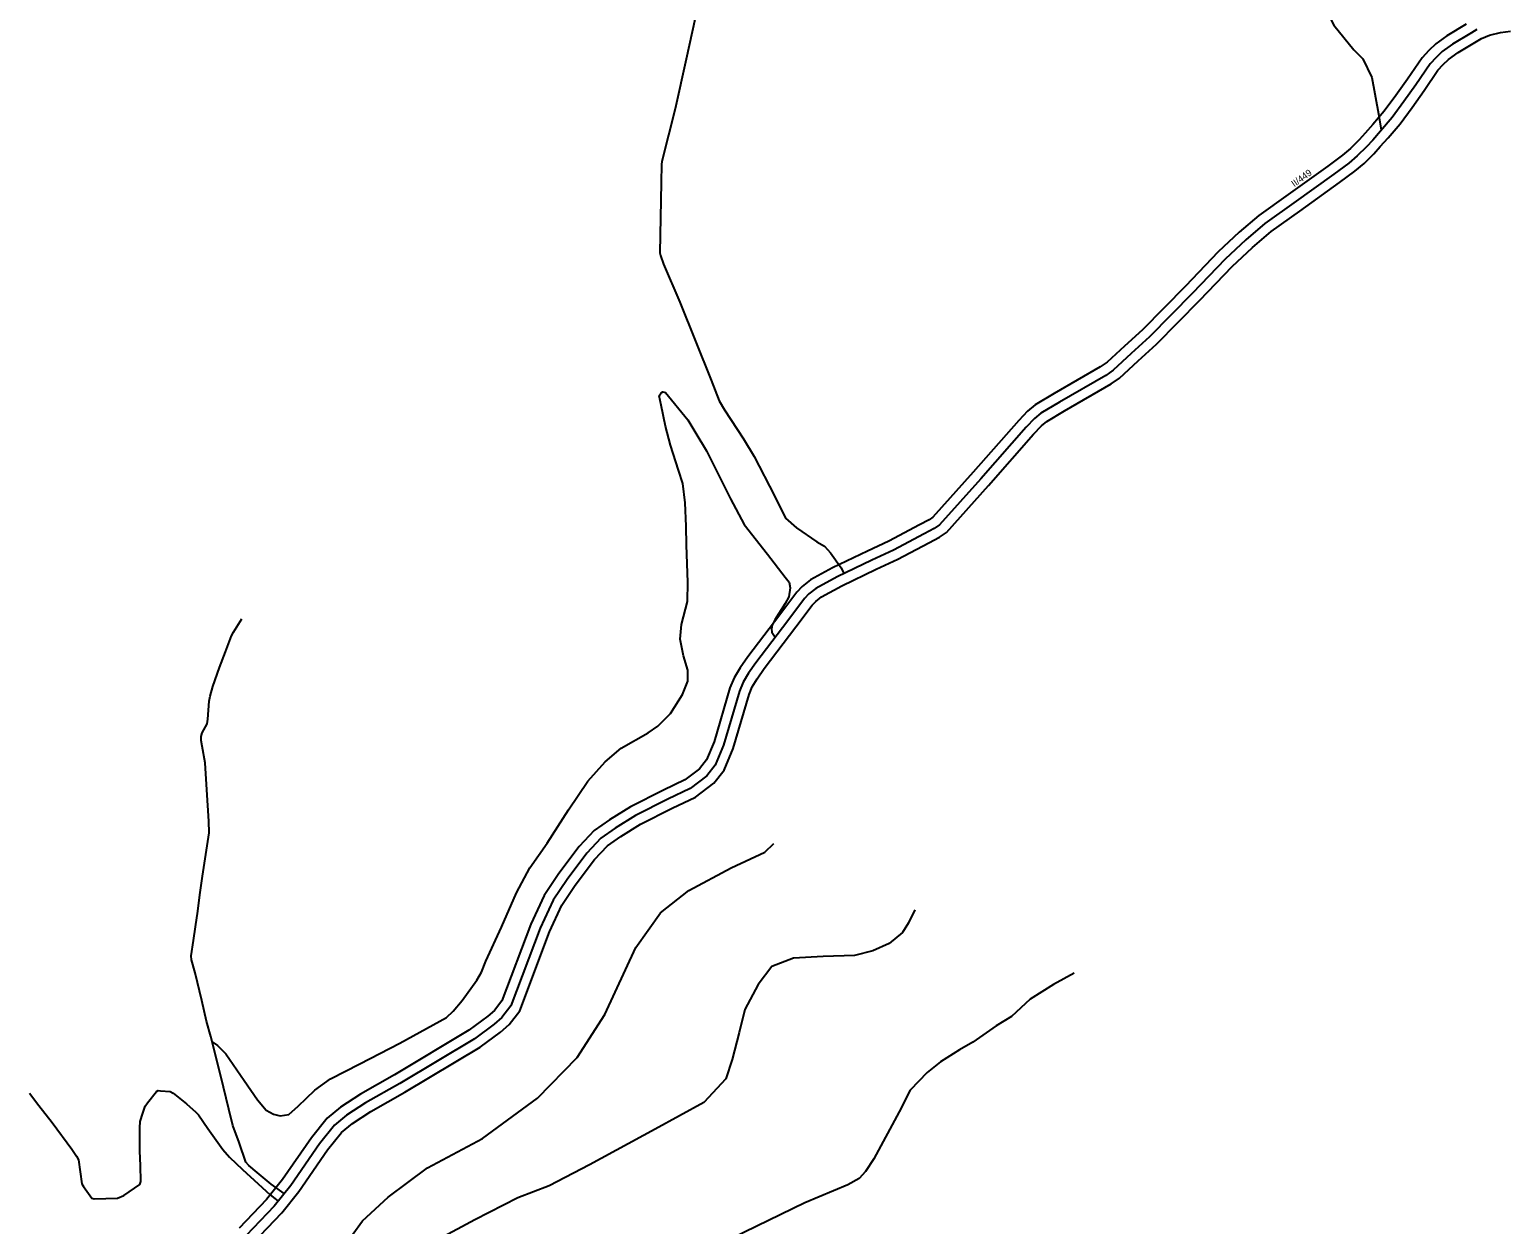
# Model space of a CAD drawing. Extents: x -547395 to -536032, y -1096268 to -1086572.
# Drawn here: x -545276 to -543076, y -1090100 to -1088325 of the extents above; entities that cross this region are included whole.
import ezdxf

# ---------------------------------------------------------------- set-up
doc = ezdxf.new("R2010")
doc.units = 0
for name, color, linetype in [('Vrstva 12', 7, 'Continuous'), ('Vrstva 5', 7, 'Continuous'), ('Vrstva 66', 7, 'Continuous')]:
    doc.layers.add(name, color=color, linetype=linetype)

msp = doc.modelspace()

# ---------------------------------------------------------------- linework, layer by layer
at = {"layer": 'Vrstva 12'}
for points in [[(-543412.7, -1088101.2), (-543404.2, -1088139.6), (-543379.7, -1088205.6), (-543357.3, -1088279.8), (-543338.3, -1088317.9), (-543308.3, -1088354.6), (-543295.1, -1088367.9), (-543281.5, -1088395.8), (-543271.6, -1088449.9), (-543267.8, -1088474.2)], [(-544286.7, -1088307.7), (-544300.1, -1088368.4), (-544316.8, -1088442.2), (-544336.3, -1088520.3), (-544337, -1088525.1), (-544337.3, -1088551.9), (-544339.2, -1088656.2), (-544338.5, -1088660.3), (-544333.8, -1088672.9), (-544309.6, -1088729.4), (-544263.2, -1088845.2), (-544251, -1088876.2), (-544243.3, -1088889.6), (-544215.1, -1088932.8), (-544199.2, -1088958.7), (-544169.2, -1089017.5), (-544152.8, -1089050.7), (-544136.4, -1089064.7), (-544106.2, -1089085.4), (-544094.6, -1089091.9), (-544085.8, -1089102.1), (-544070.2, -1089124.2), (-544066.1, -1089132.9)], [(-545004.1, -1089828.7), (-544996.4, -1089833.9), (-544983.8, -1089846.1), (-544956.6, -1089885.9), (-544937.2, -1089914.5), (-544924, -1089930.1), (-544913.4, -1089935.9), (-544903.2, -1089938.6), (-544890.6, -1089936.6), (-544876.7, -1089924), (-544851.6, -1089900.5), (-544828.8, -1089883.5), (-544784.9, -1089861.4), (-544725.6, -1089830.3), (-544656.2, -1089792.2), (-544646.4, -1089783), (-544632.8, -1089767), (-544611, -1089737.1), (-544604.2, -1089724.8), (-544597.8, -1089708.8), (-544574.5, -1089658.3), (-544552.1, -1089607.3), (-544532.7, -1089570.2), (-544506.5, -1089533.1), (-544475.1, -1089483.9), (-544446.5, -1089441.1), (-544420.7, -1089412.5), (-544396.9, -1089392.1), (-544356.8, -1089369.3), (-544342.3, -1089359.6), (-544323.3, -1089340.9), (-544305.9, -1089312.3), (-544297.8, -1089292.6), (-544297.8, -1089276.2), (-544304.2, -1089255.1), (-544309, -1089230), (-544307.1, -1089208.4), (-544298.3, -1089174.3), (-544297.9, -1089145.4), (-544299.7, -1089090.6), (-544300, -1089062.4), (-544301.5, -1089027.5), (-544305.3, -1088998.9), (-544311.7, -1088979.2), (-544323.6, -1088941.8), (-544331.1, -1088913.9), (-544337.4, -1088882.4), (-544340.4, -1088868.8), (-544337.4, -1088864.1), (-544334.7, -1088862.7), (-544330.9, -1088863.7), (-544297.9, -1088904.2), (-544285.7, -1088924.3), (-544269.9, -1088950.6), (-544234.2, -1089021.8), (-544214.2, -1089059.9), (-544179.3, -1089103.9), (-544153.1, -1089137.9), (-544147, -1089145.4), (-544145.7, -1089153.9), (-544147.7, -1089167.2), (-544153.2, -1089177), (-544168.5, -1089201.3), (-544172.4, -1089209.3), (-544173.3, -1089214.7), (-544172.8, -1089220), (-544167.9, -1089227.4)], [(-544897.3, -1090054), (-544916.5, -1090040), (-544937.6, -1090022.8), (-544950.1, -1090012.2), (-544954.2, -1090007.1), (-544964.4, -1089978), (-544973.4, -1089953), (-544979.4, -1089928.4), (-544991.7, -1089879.7), (-545006.1, -1089820.7), (-545012.6, -1089797.9), (-545019.8, -1089767), (-545029.8, -1089726), (-545034.8, -1089706.7), (-545035.3, -1089700.6), (-545031.9, -1089677.8), (-545029.2, -1089657.4), (-545025.6, -1089634.5), (-545022.7, -1089610.2), (-545018.8, -1089582.4), (-545008.9, -1089517.8), (-545009.1, -1089500.6), (-545012.2, -1089454), (-545014.9, -1089414.2), (-545019, -1089389), (-545020.5, -1089380.7), (-545020.5, -1089374.9), (-545019.1, -1089369.4), (-545011.7, -1089356.2), (-545011, -1089349), (-545008.9, -1089322.5), (-545007.2, -1089314.7), (-545003.2, -1089300.7), (-544993.3, -1089272.5), (-544984.6, -1089249.2), (-544975.5, -1089225.4), (-544972.4, -1089219.6), (-544960.2, -1089199.9)], [(-544809.5, -1090134), (-544780.9, -1090094.5), (-544742.8, -1090059.2), (-544684.4, -1090015.6), (-544602.8, -1089972.1), (-544521.2, -1089912.2), (-544462.1, -1089851.6), (-544421.3, -1089787.7), (-544375, -1089688.3), (-544338.3, -1089636.6), (-544296.2, -1089603.9), (-544233.6, -1089569.9), (-544183.3, -1089546.8), (-544169.8, -1089533.9)], [(-543960.7, -1089632.2), (-543970.2, -1089651.9), (-543979, -1089666.2), (-543998.7, -1089682.5), (-544023.2, -1089693.4), (-544050.4, -1089700.2), (-544096.6, -1089701.6), (-544140.8, -1089704.3), (-544172.8, -1089716.6), (-544193.2, -1089743.1), (-544212.9, -1089780.5), (-544221.7, -1089814.5), (-544231.9, -1089854.7), (-544241.4, -1089883.3), (-544274.1, -1089918.6), (-544346.1, -1089958.1), (-544444, -1090011.2), (-544503.9, -1090042.5), (-544550.1, -1090060.2), (-544614, -1090092.8), (-544666.7, -1090121.1)], [(-543724.1, -1089726.3), (-543754.6, -1089743.3), (-543789.3, -1089765), (-543817.2, -1089790.9), (-543839.6, -1089804.5), (-543874.3, -1089829), (-543894, -1089840.6), (-543922.6, -1089858.3), (-543942.3, -1089873.9), (-543967.4, -1089900.4), (-543983.8, -1089932.4), (-544021.5, -1090002.2), (-544033.7, -1090021.2), (-544043.2, -1090031.4), (-544060.2, -1090041), (-544124.2, -1090067.5), (-544267.6, -1090137.6)], [(-545275.5, -1089904.6), (-545261.7, -1089922.9), (-545242.2, -1089948.5), (-545212.9, -1089987.8), (-545205.7, -1089998.4), (-545202.8, -1090004), (-545197.7, -1090039.6), (-545195.6, -1090043.2), (-545182.9, -1090060.6), (-545179.5, -1090061.6), (-545144.8, -1090060.9), (-545135.4, -1090056.8), (-545112, -1090040.3), (-545110.3, -1090036.2), (-545110.8, -1090012.1), (-545111.6, -1089990.7), (-545111.9, -1089956.5), (-545111.4, -1089946.8), (-545107.3, -1089934.4), (-545103.7, -1089924.3), (-545100.6, -1089919.2), (-545086.8, -1089902.5), (-545084.4, -1089901), (-545080.9, -1089901.2), (-545066.9, -1089902.5), (-545062.2, -1089904.9), (-545042.3, -1089920.7), (-545028.4, -1089933), (-545024.4, -1089936.9), (-545010.9, -1089957.1), (-544988.7, -1089988.7), (-544978.6, -1089999.9), (-544959.1, -1090018.3), (-544936.1, -1090039.6), (-544918.4, -1090055.8), (-544911.2, -1090061.1), (-544906.2, -1090065.3)]]:
    msp.add_lwpolyline(points, dxfattribs=at)
at = {"layer": 'Vrstva 5'}
msp.add_lwpolyline([(-543125.6, -1088324.3), (-543133.9, -1088329.3), (-543161.9, -1088346.3), (-543177.3, -1088357.3), (-543186.3, -1088366), (-543195.3, -1088375.6), (-543216.3, -1088406.7), (-543234, -1088431.4), (-543251.7, -1088455.2), (-543269, -1088475.6), (-543280.4, -1088488.6), (-543289.7, -1088498.9), (-543303.4, -1088512.3), (-543316.1, -1088522.9), (-543338.4, -1088539.6), (-543397.5, -1088582), (-543440.5, -1088612.9), (-543468.9, -1088636.9), (-543499.6, -1088665.6), (-543548, -1088716.3), (-543612, -1088781.2), (-543639.1, -1088805.9), (-543665.8, -1088830.6), (-543677.1, -1088838.3), (-543745.8, -1088878.3), (-543773.2, -1088894.5), (-543782.9, -1088902.5), (-543795.2, -1088915.5), (-543862.6, -1088991.9), (-543923.7, -1089060.3), (-543931.7, -1089066), (-543946.7, -1089073.7), (-543992.4, -1089097.9), (-544024.4, -1089112.9), (-544075.8, -1089137.6), (-544107.5, -1089154.9), (-544117.9, -1089162.9), (-544124.5, -1089169.9), (-544149.2, -1089203), (-544196.6, -1089265.2), (-544207.6, -1089280.9), (-544215.6, -1089294.2), (-544221, -1089307.6), (-544244.7, -1089387.8), (-544257, -1089417.2), (-544269.7, -1089433.5), (-544294.4, -1089452.2), (-544327.4, -1089467.9), (-544375.5, -1089492.2), (-544405.8, -1089511.1), (-544426.8, -1089526.1), (-544447.9, -1089548.1), (-544477.2, -1089587.2), (-544497.9, -1089618.2), (-544516.9, -1089659.4), (-544560.6, -1089775.2), (-544574, -1089792.2), (-544585.3, -1089802.2), (-544614.7, -1089823.9), (-544725.8, -1089890.5), (-544776.5, -1089919.2), (-544805, -1089937.6), (-544822.8, -1089952.5), (-544844.8, -1089979.9), (-544887.7, -1090041.8), (-544912.1, -1090072.7), (-544953.7, -1090116.2)], dxfattribs=at)
at = {"layer": 'Vrstva 66'}
for points in [[(-543141.6, -1088316.4), (-543170.2, -1088333.8), (-543186.9, -1088345.7), (-543197, -1088355.5), (-543207.1, -1088366.3), (-543228.6, -1088398.1), (-543246.1, -1088422.5), (-543263.4, -1088445.9), (-543280.4, -1088465.8), (-543291.6, -1088478.6), (-543300.5, -1088488.5), (-543313.5, -1088501.2), (-543325.4, -1088511.2), (-543347.3, -1088527.5), (-543406.2, -1088569.8), (-543449.8, -1088601), (-543478.9, -1088625.7), (-543510.1, -1088654.9), (-543558.7, -1088705.9), (-543622.4, -1088770.4), (-543649.2, -1088794.9), (-543675.1, -1088818.8), (-543685.1, -1088825.6), (-543753.4, -1088865.4), (-543781.9, -1088882.2), (-543793.1, -1088891.5), (-543806.3, -1088905.4), (-543873.8, -1088982), (-543933.7, -1089049.1), (-543939.5, -1089053.1), (-543953.6, -1089060.4), (-543999.1, -1089084.4), (-544030.9, -1089099.3), (-544082.7, -1089124.2), (-544115.8, -1089142.3), (-544128, -1089151.8), (-544136, -1089160.2), (-544161.2, -1089193.9), (-544208.7, -1089256.3), (-544220.2, -1089272.7), (-544229.1, -1089287.5), (-544235.2, -1089302.6), (-544258.8, -1089382.8), (-544270.1, -1089409.5), (-544280.3, -1089422.8), (-544302.2, -1089439.3), (-544334, -1089454.4), (-544382.8, -1089479.2), (-544414.1, -1089498.6), (-544436.7, -1089514.7), (-544459.3, -1089538.4), (-544489.5, -1089578.5), (-544511, -1089610.9), (-544530.8, -1089653.6), (-544573.9, -1089767.7), (-544584.9, -1089781.9), (-544594.8, -1089790.5), (-544623, -1089811.4), (-544733.4, -1089877.5), (-544784.2, -1089906.3), (-544813.9, -1089925.5), (-544833.6, -1089941.9), (-544856.9, -1089970.9), (-544899.7, -1090032.9), (-544923.4, -1090062.9), (-544964.2, -1090105.5)], [(-544943.2, -1090126.9), (-544900.7, -1090082.6), (-544875.6, -1090050.7), (-544832.8, -1089988.9), (-544812.1, -1089963.1), (-544796.1, -1089949.7), (-544768.7, -1089932), (-544718.2, -1089903.4), (-544606.4, -1089836.4), (-544575.9, -1089813.9), (-544563, -1089802.5), (-544547.4, -1089782.6), (-544503.1, -1089665.2), (-544484.8, -1089625.5), (-544465, -1089595.8), (-544436.4, -1089557.8), (-544417, -1089537.5), (-544397.5, -1089523.6), (-544368.1, -1089505.3), (-544320.8, -1089481.4), (-544286.6, -1089465.1), (-544259, -1089444.3), (-544243.9, -1089424.8), (-544230.5, -1089392.9), (-544206.8, -1089312.5), (-544202.2, -1089300.9), (-544195, -1089289.1), (-544184.5, -1089274), (-544137.3, -1089212), (-544113.1, -1089179.6), (-544107.8, -1089174.1), (-544099.3, -1089167.5), (-544069, -1089150.9), (-544018, -1089126.4), (-543985.7, -1089111.3), (-543939.8, -1089087), (-543923.9, -1089078.9), (-543913.6, -1089071.6), (-543851.4, -1089001.9), (-543784.2, -1088925.6), (-543772.6, -1088913.5), (-543764.5, -1088906.8), (-543738.2, -1088891.2), (-543669.1, -1088851), (-543656.4, -1088842.4), (-543628.9, -1088816.9), (-543601.6, -1088792), (-543537.2, -1088726.8), (-543489, -1088676.3), (-543458.9, -1088648.1), (-543431.3, -1088624.7), (-543388.7, -1088594.2), (-543329.6, -1088551.7), (-543306.8, -1088534.7), (-543293.3, -1088523.4), (-543278.9, -1088509.3), (-543269.2, -1088498.5), (-543257.7, -1088485.4), (-543239.9, -1088464.6), (-543221.9, -1088440.2), (-543204, -1088415.2), (-543183.5, -1088385), (-543175.6, -1088376.5), (-543167.7, -1088368.8), (-543153.7, -1088358.8), (-543126.2, -1088342.1), (-543118.8, -1088337.7), (-543107.1, -1088332.9), (-543090.7, -1088328.7), (-543075.9, -1088326.8)]]:
    msp.add_lwpolyline(points, dxfattribs=at)

# ---------------------------------------------------------------- texts
at = {"layer": 'Vrstva 5'}
msp.add_text('II/449', height=10, rotation=35.6559, dxfattribs=at).set_placement((-543396.9, -1088558.9))

doc.saveas('drawing.dxf')
